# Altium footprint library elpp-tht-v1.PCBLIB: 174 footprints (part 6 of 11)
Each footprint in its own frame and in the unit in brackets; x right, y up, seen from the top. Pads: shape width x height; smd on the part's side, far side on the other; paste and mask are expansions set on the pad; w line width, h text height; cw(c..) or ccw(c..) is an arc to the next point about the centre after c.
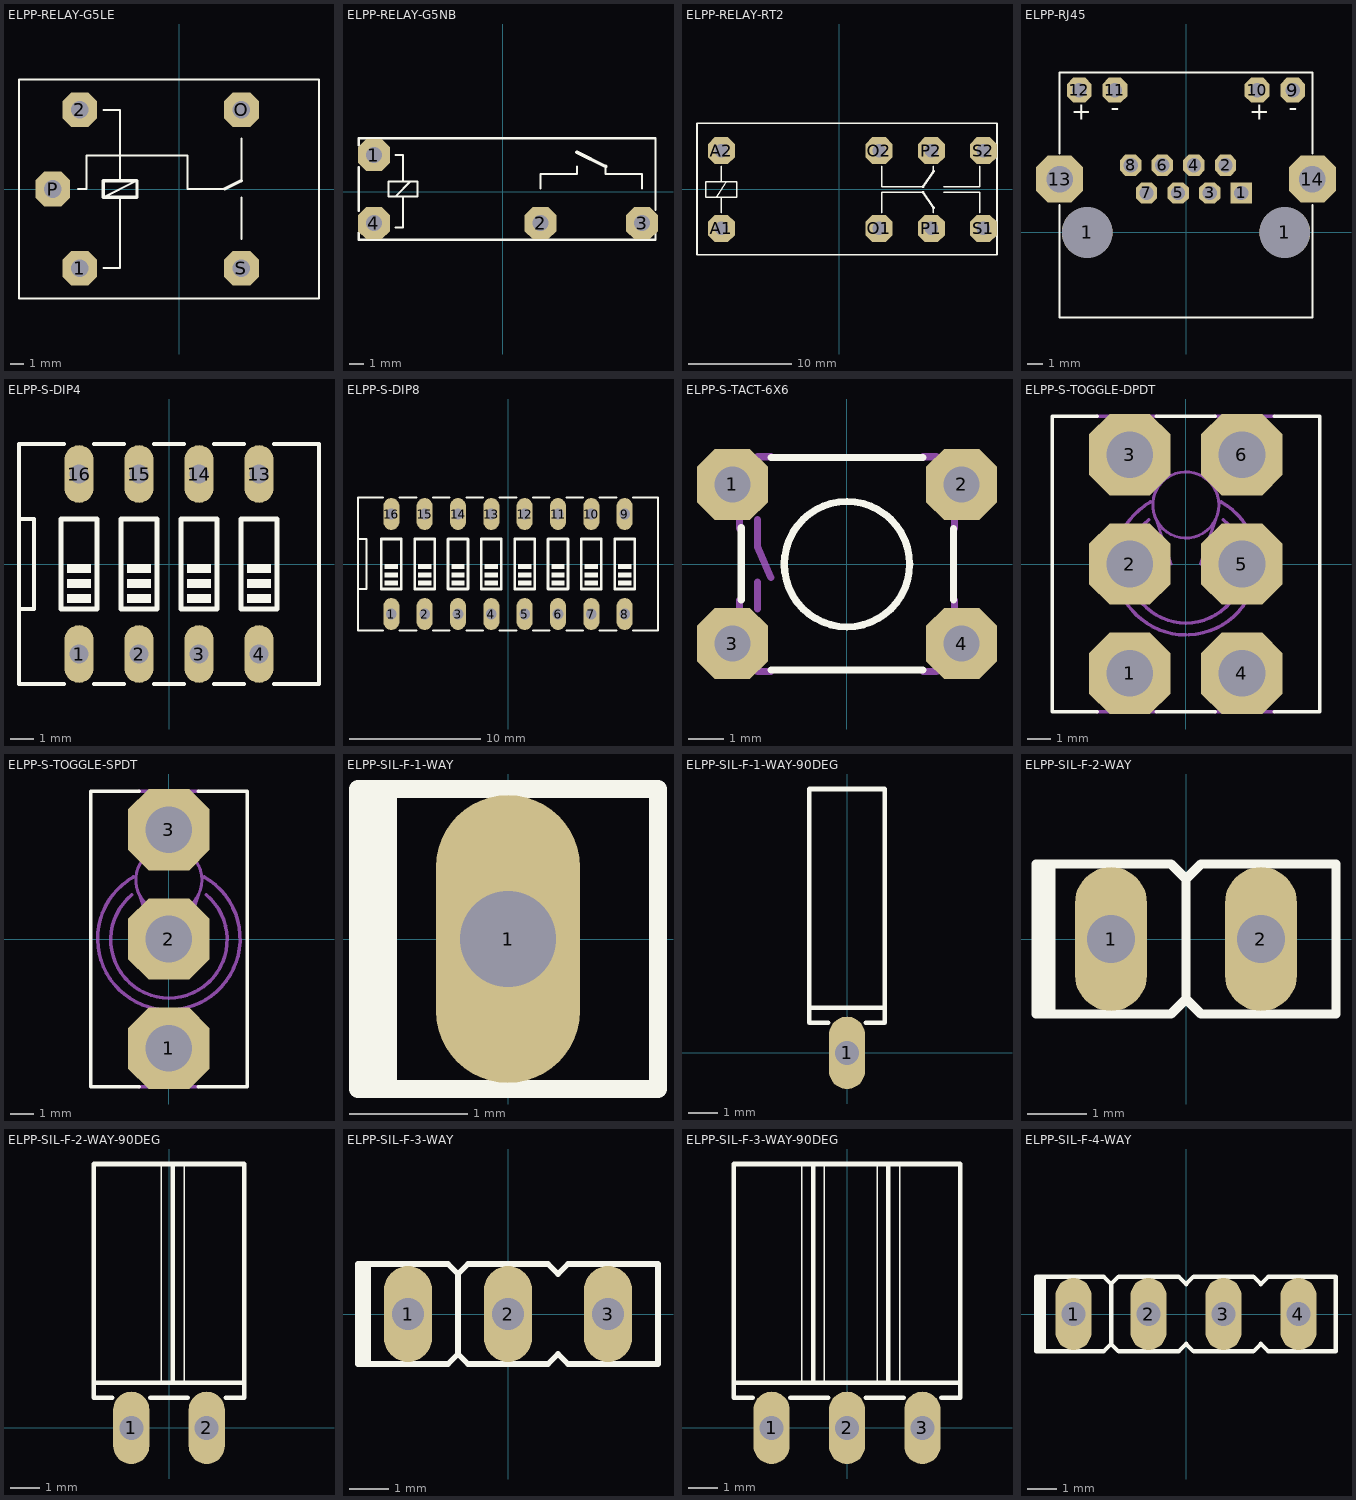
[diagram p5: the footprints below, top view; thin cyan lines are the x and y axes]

## ELPP-RELAY-G5LE [mil]
pads (5):
  oct 103x103 hole 52: 1(-295,-235) 2(-295,235) O(185,235) P(-375,0) S(185,-235)
Top Overlay:
  lines w6: -300,0 -275,0 -275,100 25,100 25,0 135,0 ; -225,-235 -175,-235 -175,-25 ; -225,-25 -125,25 ; -225,235 -175,235 -175,25 ; 185,-148 185,-25 ; 185,27 185,150 ; -475,-325 415,-325 415,325 -475,325 -475,-325
  lines w10: 135,0 185,25 ; -225,-25 -175,-25 -125,-25 -125,25 -175,25 -225,25 -225,-25
Mechanical 2:
  text ">NAME" at -450,345 h42.5
Mechanical 4:
  text ">VALUE" at 375,-300 h42.5

## ELPP-RELAY-G5NB [mil]
pads (4):
  oct 87x87 hole 44: 1(-350,100) 2(103,-85.04) 3(379,-85.04) 4(-350,-85.04)
Top Overlay:
  lines w6: -391.34,-110.63 -391.34,-130.31 416,-130.31 416,-108.46 ; -391.34,-51.57 -391.34,67 ; -391.34,126 -391.34,146 416,146 416,-49.41 ; -290.94,-96.85 -271.26,-96.85 -271.26,-12.2 ; -290.94,100 -271.26,100 -271.26,28 ; 103,10 103,49 202,49 202,69 ; 280,69 280,49 379,49 379,10 ; -290.94,-12.2 -310.63,-12.2 -310.63,28 -271.26,28 ; -290.94,-12.2 -271.26,-12.2 ; -290.94,-12.2 -251.57,28 ; -271.26,-12.2 -231.89,-12.2 -231.89,28 -251.57,28 ; -271.26,28 -251.57,28
  lines w10: 202,108 280,69
Mechanical 2:
  text ">NAME" at -389.37,160 h42.5
Mechanical 4:
  text ">VALUE" at -389.37,-195.28 h42.5

## ELPP-RELAY-RT2 [mil]
pads (8):
  oct 103x103 hole 52: A1(-450,-150) A2(-450,146) O1(151,-150) O2(151,146) P1(350,-150) P2(350,146) S1(548,-150) S2(548,146)
Top Overlay:
  lines w6: -450,-90.94 -450,-31.89 ; -450,87 -450,28 ; 161,-90.94 161,-12.2 318,-12.2 ; 161,87 161,8 318,8 ; 358,-90.94 358,-71.26 ; 358,67 358,87 ; 397,-12.2 535,-12.2 535,-90.94 ; 397,8 535,8 535,87 ; -469.69,-31.89 -509.06,-31.89 -509.06,28 -450,28 ; -469.69,-31.89 -450,-31.89 ; -469.69,-31.89 -430.31,28 ; -450,-31.89 -390.94,-31.89 -390.94,28 -430.31,28 ; -450,28 -430.31,28 ; -542.52,-250 -542.52,250 600,250 600,-250 -542.52,-250
  lines w10: 318,-12.2 358,-71.26 ; 318,8 358,67
Mechanical 2:
  text ">NAME" at -519.68,281 h42.5
Mechanical 4:
  text ">VALUE" at -528.74,-325.59 h42.5

## ELPP-RJ45 [mil]
pads (16):
  round 128 hole 128: 1(-250,0) 1(250,0)
  rect 54x54 hole 36: 1(140,100)
  oct 54x54 hole 36: 2(100,170) 3(60,100) 4(20,170) 5(-20,100) 6(-60,170) 7(-100,100) 8(-140,170)
  oct 63x63 hole 36: 9(270,360) 10(180,360) 11(-180,360) 12(-270,360)
  oct 119x119 hole 67: 13(-320,135) 14(320,135)
Top Overlay:
  lines w5: -320,70 -320,-215 320,-215 320,70 ; -320,200 -320,405 320,405 320,200
  text "+" at -290,270 h77.5
  text "+" at 160,270 h77.5
  text "-" at -190,280 h77.5
  text "-" at 260,280 h77.5
Mechanical 2:
  text ">NAME" at -300,430 h42.5
Mechanical 4:
  text ">VALUE" at -130,-110 h42.5

## ELPP-S-DIP4 [mil]
pads (8):
  oval 48x96 hole 32: 1(-150,-150) 2(-50,-150) 3(50,-150) 4(150,-150) 13(150,150) 14(50,150) 15(-50,150) 16(-150,150)
Top Overlay:
  rectangle: 130,-15 170,0
  rectangle: 130,-40 170,-25
  rectangle: 130,-65 170,-50
  rectangle: 30,-15 70,0
  rectangle: 30,-40 70,-25
  rectangle: 30,-65 70,-50
  rectangle: -70,-15 -30,0
  rectangle: -70,-40 -30,-25
  rectangle: -70,-65 -30,-50
  rectangle: -170,-15 -130,0
  rectangle: -170,-40 -130,-25
  rectangle: -170,-65 -130,-50
  lines w6: -175,-200 -250,-200 -250,-75 ; -175,200 -250,200 -250,75 ; -125,-200 -75,-200 ; -125,200 -75,200 ; -25,-200 25,-200 ; -25,200 25,200 ; 75,-200 125,-200 ; 75,200 125,200 ; 175,-200 250,-200 250,200 175,200 ; -250,-75 -250,75 ; -250,-75 -225,-75 -225,75 -250,75
  lines w8: -180,-75 -180,75 -120,75 -120,-75 -180,-75 ; -80,-75 -80,75 -20,75 -20,-75 -80,-75 ; 20,-75 20,75 80,75 80,-75 20,-75 ; 120,-75 120,75 180,75 180,-75 120,-75
Mechanical 2:
  text ">NAME" at -230,210 h42.5
Mechanical 4:
  text ">VALUE" at 50,210 h42.5
Mechanical 16:
  text "1" at -160,-165 h93
  text "ON" at -200,100 h93
  text "2" at -70,-165 h93
  text "3" at 30,-165 h93
  text "4" at 130,-165 h93

## ELPP-S-DIP8 [mil]
pads (16):
  oval 48x96 hole 32: 1(-350,-150) 2(-250,-150) 3(-150,-150) 4(-50,-150) 5(50,-150) 6(150,-150) 7(250,-150) 8(350,-150) 9(350,150) 10(250,150) 11(150,150) 12(50,150) 13(-50,150) 14(-150,150) 15(-250,150) 16(-350,150)
Top Overlay:
  rectangle: 330,-15 370,0
  rectangle: 330,-40 370,-25
  rectangle: 330,-65 370,-50
  rectangle: 230,-15 270,0
  rectangle: 230,-40 270,-25
  rectangle: 230,-65 270,-50
  rectangle: 130,-15 170,0
  rectangle: 130,-40 170,-25
  rectangle: 130,-65 170,-50
  rectangle: 30,-15 70,0
  rectangle: 30,-40 70,-25
  rectangle: 30,-65 70,-50
  rectangle: -70,-15 -30,0
  rectangle: -70,-40 -30,-25
  rectangle: -70,-65 -30,-50
  rectangle: -170,-15 -130,0
  rectangle: -170,-40 -130,-25
  rectangle: -170,-65 -130,-50
  rectangle: -270,-15 -230,0
  rectangle: -270,-40 -230,-25
  rectangle: -270,-65 -230,-50
  rectangle: -370,-15 -330,0
  rectangle: -370,-40 -330,-25
  rectangle: -370,-65 -330,-50
  lines w6: -375,-200 -450,-200 -450,-75 ; -375,200 -450,200 -450,75 ; -325,-200 -275,-200 ; -325,200 -275,200 ; -225,-200 -175,-200 ; -225,200 -175,200 ; -125,-200 -75,-200 ; -125,200 -75,200 ; -25,-200 25,-200 ; -25,200 25,200 ; 75,-200 125,-200 ; 75,200 125,200 ; 175,-200 225,-200 ; 175,200 225,200 ; 275,-200 325,-200 ; 275,200 325,200 ; 375,-200 450,-200 450,200 375,200 ; -450,-75 -450,75 ; -450,-75 -425,-75 -425,75 -450,75
  lines w8: -380,-75 -380,75 -320,75 -320,-75 -380,-75 ; -280,-75 -280,75 -220,75 -220,-75 -280,-75 ; -180,-75 -180,75 -120,75 -120,-75 -180,-75 ; -80,-75 -80,75 -20,75 -20,-75 -80,-75 ; 20,-75 20,75 80,75 80,-75 20,-75 ; 120,-75 120,75 180,75 180,-75 120,-75 ; 220,-75 220,75 280,75 280,-75 220,-75 ; 320,-75 320,75 380,75 380,-75 320,-75
Mechanical 2:
  text ">NAME" at -430,210 h42.5
Mechanical 4:
  text ">VALUE" at -150,210 h42.5
Mechanical 16:
  text "1" at -360,-165 h93
  text "ON" at -400,100 h93
  text "2" at -270,-165 h93
  text "3" at -170,-165 h93
  text "4" at -70,-165 h93
  text "5" at 30,-165 h93
  text "6" at 130,-165 h93
  text "7" at 230,-165 h93
  text "8" at 330,-165 h93

## ELPP-S-TACT-6X6 [mil]
pads (4):
  oct 79x79 hole 40: 1(-127.95,89) 2(128,89) 3(-127.95,-88.58) 4(128,-88.58)
Top Overlay:
  circle w8: c0,0 r70
  lines w8: -118.11,-40 -118.11,41 ; -85,-118.11 85,-118.11 ; -85,119 85,119 ; 119,-40 119,40
Mechanical 2:
  text ">NAME" at -100,150 h42.5
Mechanical 4:
  text ">VALUE" at -100,-200 h42.5
Mechanical 16:
  lines w8: -120,-40 -120,-100 -100,-120 -85,-120 ; -120,40 -120,100 -100,120 -85,120 ; -100,-50 -100,-20 ; -100,50 -100,20 -85,-15 ; 85,-120 100,-120 120,-100 120,-40 ; 85,120 100,120 120,100 120,40

## ELPP-S-TOGGLE-DPDT [mil]
pads (6):
  oct 138x138 hole 79: 1(-95,-185) 2(-95,0) 3(-95,185) 4(95,-185) 5(95,0) 6(95,185)
Top Overlay:
  lines w6: -226.5,-250 -226.5,250 ; -225,-250 -150,-250 ; -225,250 -150,250 ; -50,-250 50,-250 ; -50,250 50,250 ; 150,-250 225,-250 ; 150,250 225,250 ; 227,-250 227,250
Mechanical 2:
  text ">NAME" at -125,275 h42.5
Mechanical 4:
  text ">VALUE" at -125,-325 h42.5
Mechanical 16:
  circle w5: c0,100 r56
  lines w5: -50,75 -25,0 ; 25,0 50,75
  lines w6: -150,-250 -50,-250 ; -150,250 -50,250 ; -62.5,75 ccw(c0.43,-1.19) 0,-100 ccw(c-0.18,-1.1) 63,75 ; -60,105 ccw(c-0.12,0.47) 0,-120 ; 5,-120 ccw(c0.1,0.42) 60,105 ; 50,-250 150,-250 ; 50,250 150,250

## ELPP-S-TOGGLE-SPDT [mil]
pads (3):
  oct 138x138 hole 79: 1(0,-185) 2(0,0) 3(0,185)
Top Overlay:
  lines w6: -50,-250 -132.5,-250 -132.5,250 -50,250 ; 50,-250 133,-250 133,250 50,250
Mechanical 2:
  text ">NAME" at -125,275 h42.5
Mechanical 4:
  text ">VALUE" at -125,-325 h42.5
Mechanical 16:
  circle w5: c0,100 r56
  lines w5: -50,75 -25,0 ; 25,0 50,75
  lines w6: -62.5,75 ccw(c0.43,-1.19) 0,-100 ccw(c-0.18,-1.1) 63,75 ; -60,105 ccw(c-0.12,0.47) 0,-120 ; -50,-250 50,-250 ; -50,250 50,250 ; 5,-120 ccw(c0.1,0.42) 60,105

## ELPP-SIL-F-1-WAY [mil]
pads (1):
  oval 48x96 hole 32: 1(0,0)
Top Overlay:
  lines w6: -50,-50 -50,50 ; -50,-50 -45,-50 ; -50,-50 50,-50 50,50 -50,50 ; -50,50 -45,50 ; -45,-50 -40,-50 -40,50 -45,50 ; -45,-50 -45,50
Mechanical 2:
  text ">NAME" at -50,65 h42.5
Mechanical 4:
  text ">VALUE" at -50,-135 h42.5
Mechanical 16:
  rectangle: -5,10 5,30
  rectangle: -5,-30 5,-10
  lines w6: -20,-20 -20,20 -10,20 -10,30 10,30 10,20 20,20 20,-20 10,-20 10,-30 -10,-30 -10,-20 -20,-20

## ELPP-SIL-F-1-WAY-90DEG [mil]
pads (1):
  oval 48x96 hole 32: 1(0,0)
Top Overlay:
  lines w6: -25,40 -50,40 -50,60 ; 25,40 50,40 50,60 ; -50,60 -50,350 40,350 50,350 50,60 ; -50,60 40,60 50,60
Mechanical 2:
  text ">NAME" at -70,40 h42.5
Mechanical 4:
  text ">VALUE" at 110,50 h42.5
Mechanical 16:
  rectangle: -10,0 10,40

## ELPP-SIL-F-2-WAY [mil]
pads (2):
  oval 48x96 hole 32: 1(-50,0) 2(50,0)
Top Overlay:
  lines w6: -95,-50 -100,-50 -100,50 -95,50 ; -95,-50 -90,-50 ; -95,-50 -95,50 ; -95,50 -90,50 ; -90,-50 -10,-50 0,-40 ; -90,-50 -90,50 ; -90,50 -10,50 0,40 ; 0,-40 10,-50 100,-50 100,50 10,50 0,40 ; 0,-40 0,40
Mechanical 2:
  text ">NAME" at -100,65 h42.5
Mechanical 4:
  text ">VALUE" at -100,-135 h42.5
Mechanical 16:
  rectangle: -55,10 -45,30
  rectangle: -55,-30 -45,-10
  rectangle: 45,10 55,30
  rectangle: 45,-30 55,-10
  lines w6: -70,-20 -70,20 -60,20 -60,30 -40,30 -40,20 -30,20 -30,-20 -40,-20 -40,-30 -60,-30 -60,-20 -70,-20 ; 30,-20 30,20 40,20 40,30 60,30 60,20 70,20 70,-20 60,-20 60,-30 40,-30 40,-20 30,-20

## ELPP-SIL-F-2-WAY-90DEG [mil]
pads (2):
  oval 48x96 hole 32: 1(-50,0) 2(50,0)
Top Overlay:
  lines w2: -10,60 -10,350 ; 20,60 20,350
  lines w6: -75,40 -100,40 -100,60 ; -25,40 25,40 ; 75,40 100,40 100,60 ; -100,60 -100,350 -10,350 5,350 ; -100,60 -10,60 5,60 ; 5,60 20,60 ; 5,60 90,60 ; 5,60 20,60 ; 5,60 90,60 ; 5,60 20,60 ; 5,60 90,60 ; 5,60 20,60 ; 5,60 5,350 ; 5,350 20,350 ; 5,350 90,350 ; 5,350 20,350 ; 5,350 90,350 ; 5,350 20,350 ; 5,350 90,350 ; 5,350 20,350 ; 20,60 90,60 ; 20,60 90,60 ; 20,60 90,60 ; 20,60 100,60 ; 20,350 90,350 ; 20,350 90,350 ; 20,350 90,350 ; 20,350 100,350 100,60
Mechanical 2:
  text ">NAME" at -120,40 h42.5
Mechanical 4:
  text ">VALUE" at 160,50 h42.5
Mechanical 16:
  rectangle: -60,0 -40,40
  rectangle: 40,0 60,40
  text "2" at 80,100 h77.5
  text "1" at -20,100 h77.5

## ELPP-SIL-F-3-WAY [mil]
pads (3):
  oval 48x96 hole 32: 1(-100,0) 2(0,0) 3(100,0)
Top Overlay:
  lines w6: -145,-50 -150,-50 -150,50 -145,50 ; -145,-50 -140,-50 ; -145,-50 -145,50 ; -145,50 -140,50 ; -140,-50 -60,-50 -50,-40 ; -140,-50 -140,50 ; -140,50 -60,50 -50,40 ; -50,-40 -40,-50 40,-50 50,-40 60,-50 150,-50 150,50 60,50 50,40 40,50 -40,50 -50,40 ; -50,-40 -50,40
Mechanical 2:
  text ">NAME" at -150,65 h42.5
Mechanical 4:
  text ">VALUE" at -150,-135 h42.5
Mechanical 16:
  rectangle: -105,10 -95,30
  rectangle: -105,-30 -95,-10
  rectangle: -5,10 5,30
  rectangle: -5,-30 5,-10
  rectangle: 95,10 105,30
  rectangle: 95,-30 105,-10
  lines w6: -120,-20 -120,20 -110,20 -110,30 -90,30 -90,20 -80,20 -80,-20 -90,-20 -90,-30 -110,-30 -110,-20 -120,-20 ; -20,-20 -20,20 -10,20 -10,30 10,30 10,20 20,20 20,-20 10,-20 10,-30 -10,-30 -10,-20 -20,-20 ; 80,-20 80,20 90,20 90,30 110,30 110,20 120,20 120,-20 110,-20 110,-30 90,-30 90,-20 80,-20

## ELPP-SIL-F-3-WAY-90DEG [mil]
pads (3):
  oval 48x96 hole 32: 1(-100,0) 2(0,0) 3(100,0)
Top Overlay:
  lines w2: -60,60 -60,350 ; -30,60 -30,350 ; 40,60 40,350 ; 70,60 70,350
  lines w6: -125,40 -150,40 -150,60 ; -75,40 -25,40 ; 25,40 75,40 ; 125,40 150,40 150,60 ; -150,60 -150,350 -60,350 -45,350 ; -150,60 -60,60 -45,60 ; -45,60 -30,60 ; -45,60 140,60 70,60 ; -45,60 -30,60 ; -45,60 -45,350 ; -45,350 -30,350 ; -45,350 140,350 70,350 ; -45,350 -30,350 ; -30,60 40,60 ; -30,60 40,60 ; -30,350 40,350 ; -30,350 40,350 ; 40,60 55,60 ; 40,60 55,60 ; 40,350 55,350 ; 40,350 55,350 ; 55,60 70,60 ; 55,60 70,60 ; 55,60 55,350 ; 55,350 70,350 ; 55,350 70,350 ; 70,60 150,60 ; 70,350 150,350 150,60
Mechanical 2:
  text ">NAME" at -170,40 h42.5
Mechanical 4:
  text ">VALUE" at 210,50 h42.5
Mechanical 16:
  rectangle: -110,0 -90,40
  rectangle: -10,0 10,40
  rectangle: 90,0 110,40
  text "2" at 30,100 h77.5
  text "3" at 130,100 h77.5
  text "1" at -70,100 h77.5

## ELPP-SIL-F-4-WAY [mil]
pads (4):
  oval 48x96 hole 32: 1(-150,0) 2(-50,0) 3(50,0) 4(150,0)
Top Overlay:
  lines w6: -195,-50 -200,-50 -200,50 -195,50 ; -195,-50 -190,-50 ; -195,-50 -195,50 ; -195,50 -190,50 ; -190,-50 -110,-50 -100,-40 ; -190,-50 -190,50 ; -190,50 -110,50 -100,40 ; -100,-40 -90,-50 -10,-50 0,-40 10,-50 90,-50 100,-40 110,-50 200,-50 200,50 110,50 100,40 90,50 10,50 0,40 -10,50 -90,50 -100,40 ; -100,-40 -100,40
Mechanical 2:
  text ">NAME" at -200,65 h42.5
Mechanical 4:
  text ">VALUE" at -200,-135 h42.5
Mechanical 16:
  rectangle: -155,10 -145,30
  rectangle: -155,-30 -145,-10
  rectangle: -55,10 -45,30
  rectangle: -55,-30 -45,-10
  rectangle: 45,10 55,30
  rectangle: 45,-30 55,-10
  rectangle: 145,10 155,30
  rectangle: 145,-30 155,-10
  lines w6: -170,-20 -170,20 -160,20 -160,30 -140,30 -140,20 -130,20 -130,-20 -140,-20 -140,-30 -160,-30 -160,-20 -170,-20 ; -70,-20 -70,20 -60,20 -60,30 -40,30 -40,20 -30,20 -30,-20 -40,-20 -40,-30 -60,-30 -60,-20 -70,-20 ; 30,-20 30,20 40,20 40,30 60,30 60,20 70,20 70,-20 60,-20 60,-30 40,-30 40,-20 30,-20 ; 130,-20 130,20 140,20 140,30 160,30 160,20 170,20 170,-20 160,-20 160,-30 140,-30 140,-20 130,-20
